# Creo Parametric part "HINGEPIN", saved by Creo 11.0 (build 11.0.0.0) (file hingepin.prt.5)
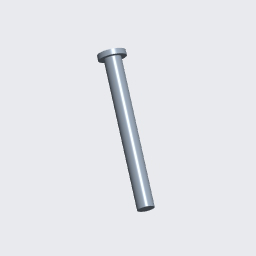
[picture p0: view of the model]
Units: Inch lbm Second (Pro/E Default); INCH, POUND, SECS

Created from: XX_INLBS_PART_SOLID_ABS.PRT

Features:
  1. datum plane "RIGHT"
  2. datum plane "TOP"
  3. datum plane "FRONT"
  4. coordinate system
  5. datum axis "A_1"
  6. sketch "Sketch 1"
  7. revolve "Revolve 1"

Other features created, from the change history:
  sketch "Sketch 1"
  extrusion "Extrude 1"

Surfaces: 3 plane, 2 cylinder, 2 cone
